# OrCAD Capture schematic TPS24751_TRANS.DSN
size Custom; title: TPS24751: 12A Integrated Hot-Swap with Current Monitor; rev: 1.0; note: Datasheet: SLVSC87  EVM UG: SLVU968
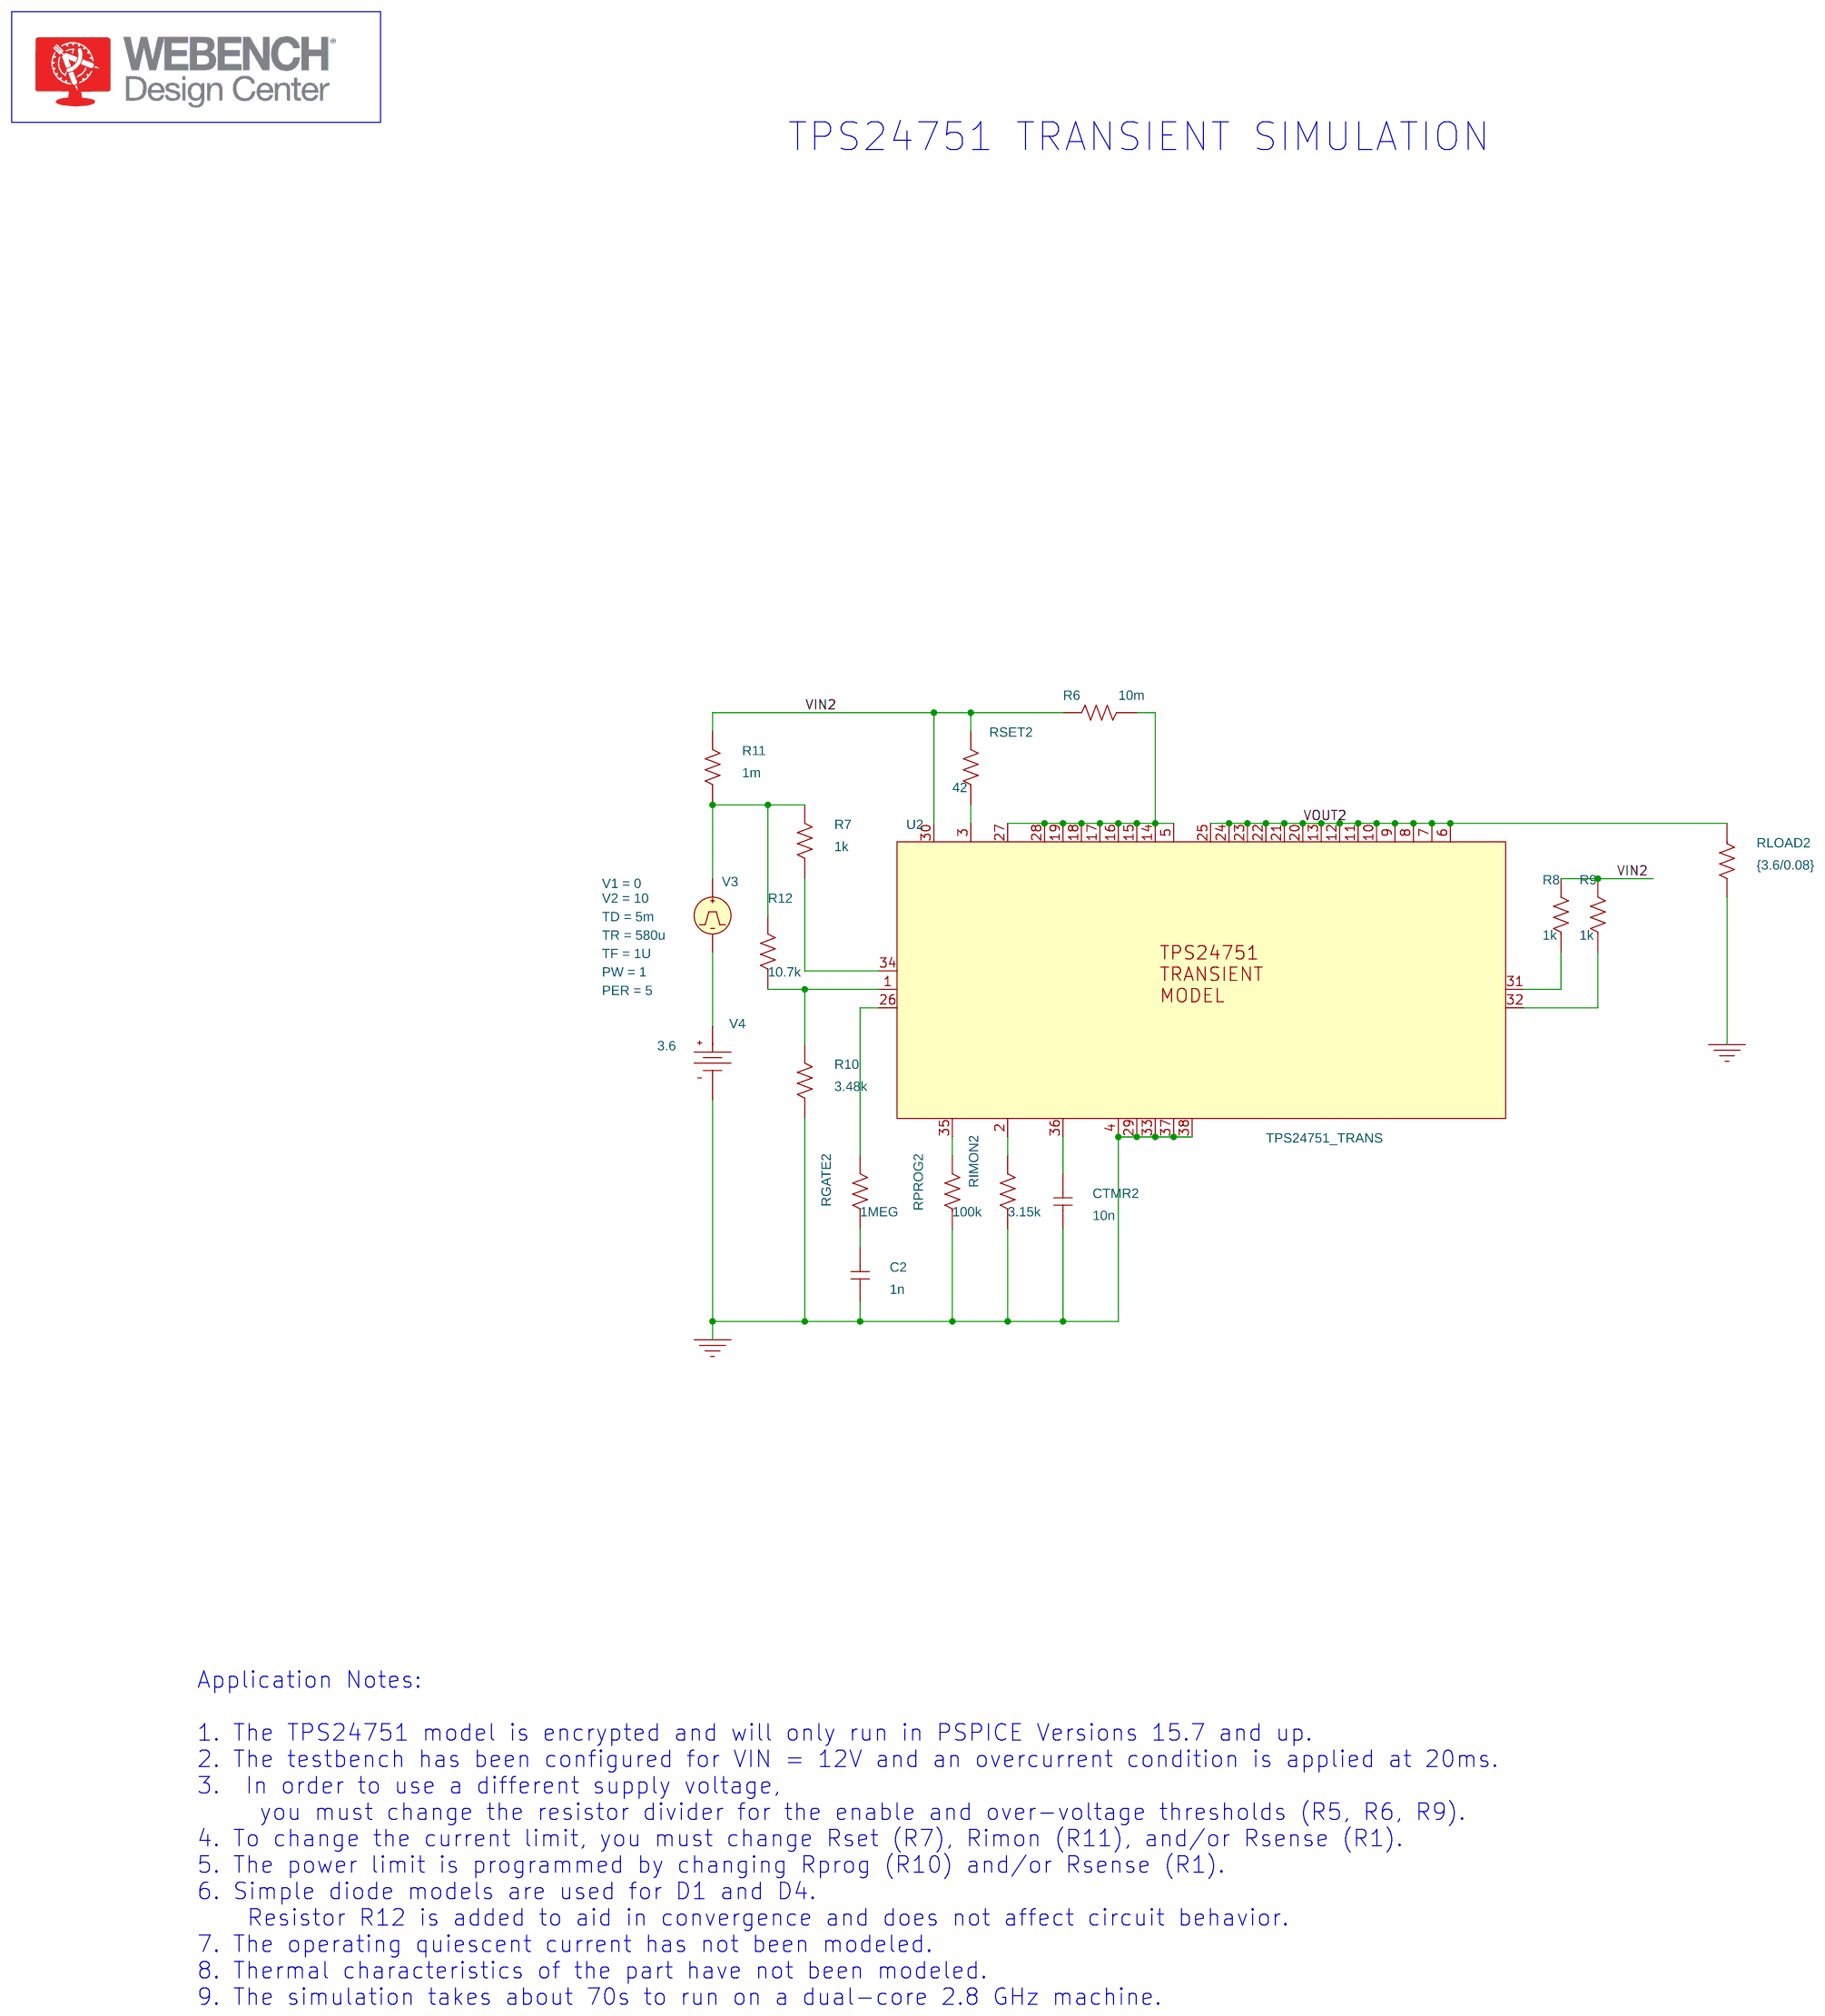
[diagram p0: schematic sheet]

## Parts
C2  1n  [RAD/CK05]
CTMR2  10n  [RAD/CK05]
R6  10m  [AX/RC05]
R7  1k  [AX/RC05]
R8  1k  [AX/RC05]
R9  1k  [AX/RC05]
R10  3.48k  [AX/RC05]
R11  1m  [AX/RC05]
R12  10.7k  [AX/RC05]
RGATE2  1MEG  [AX/RC05]
RIMON2  3.15k  [AX/RC05]
RLOAD2  {3.6/0.08}  [AX/RC05]
RPROG2  100k  [AX/RC05]
RSET2  42  [AX/RC05]
U2  TPS24751_TRANS
V3  VPULSE
V4  VDC

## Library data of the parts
C2 CTMR2 = C
R6-R12 RGATE2 RIMON2 RLOAD2 RPROG2 RSET2 = R
U2 = TPS24751_TRANS_0: PSpiceTemplate: X^@REFDES %OV %IMON %SET %GND_0 %DRAIN_0 %OUT_0 %OUT_1 %OUT_2 %OUT_3 %OUT_4 %OUT_5 %OUT_6 %OUT_7 %DRAIN_1 %DRAIN_2 %DRAIN_3 %DRAIN_4 %DRAIN_5 %DRAIN_6 %OUT_8 %OUT_9 %OUT_10 %OUT_11 %OUT_12 %OUT_13 %GATE %SENSE %DRAIN_7 %GND_1 %VCC %FLTB %PGB %GND_2 %EN %PROG %TIMER %GND_3 %GND_4 @MODEL
V3 = VPULSE: PER: 5; PW: 1; TD: 5m; TF: 1U; TR: 580u; V1: 0; V2: 10
V4 = VDC: DC: 3.6

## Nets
VIN2: R6.2 R8.2 R9.2 R11.2 RSET2.2 U2.30(VCC)
0: C2.1 CTMR2.1 R10.1 RIMON2.1 RLOAD2.2 RPROG2.1 U2.4(GND_0) U2.29(GND_1) U2.33(GND_2) U2.37(GND_3) U2.38(GND_4) V4.1(-)
VOUT2: RLOAD2.1 U2.6(OUT_0) U2.7(OUT_1) U2.8(OUT_2) U2.9(OUT_3) U2.10(OUT_4) U2.11(OUT_5) U2.12(OUT_6) U2.13(OUT_7) U2.20(OUT_8) U2.21(OUT_9) U2.22(OUT_10) U2.23(OUT_11) U2.24(OUT_12) U2.25(OUT_13)
N16731716: V3.2(-) V4.0(+)
N16731720: R7.2 R11.1 R12.2 V3.1(+)
N16732621: R7.1 U2.34(EN)
N16732627: R10.2 R12.1 U2.1(OV)
N16732655: R6.1 U2.5(DRAIN_0) U2.14(DRAIN_1) U2.15(DRAIN_2) U2.16(DRAIN_3) U2.17(DRAIN_4) U2.18(DRAIN_5) U2.19(DRAIN_6) U2.27(SENSE) U2.28(DRAIN_7)
N16732695: RSET2.1 U2.3(SET)
N16732707: R8.1 U2.31(FLTB)
N16732711: R9.1 U2.32(PGB)
N16732731: CTMR2.2 U2.36(TIMER)
N16732733: RIMON2.2 U2.2(IMON)
N16732735: RPROG2.2 U2.35(PROG)
N16732737: RGATE2.2 U2.26(GATE)
N16732745: C2.2 RGATE2.1

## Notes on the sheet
- TPS24751 TRANSIENT SIMULATION
- Application Notes:
  1. The TPS24751 model is encrypted and will only run in PSPICE Versions 15.7 and up.
  2. The testbench has been configured for VIN = 12V and an overcurrent condition is applied at 20ms.
  3.  In order to use a different supply voltage,
       you must change the resistor divider for the enable and over-voltage thresholds (R5, R6, R9).
  4. To change the current limit, you must change Rset (R7), Rimon (R11), and/or Rsense (R1).
  5. The power limit is programmed by changing Rprog (R10) and/or Rsense (R1).
  6. Simple diode models are used for D1 and D4.
      Resistor R12 is added to aid in convergence and does not affect circuit behavior.
  7. The operating quiescent current has not been modeled.
  8. Thermal characteristics of the part have not been modeled.
  9. The simulation takes about 70s to run on a dual-core 2.8 GHz machine.
